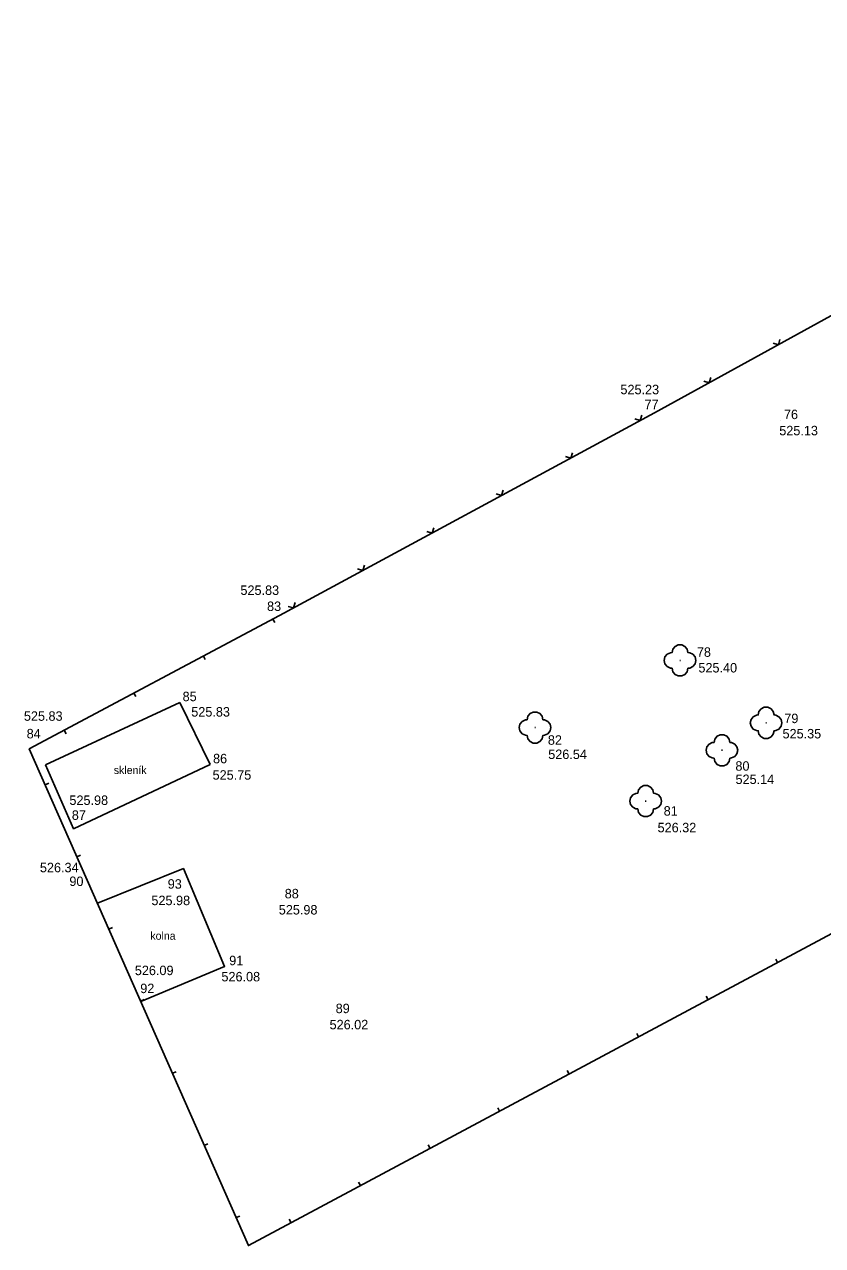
# Model space of a CAD drawing. Extents: x -871052.2 to -870965.1, y -1009970.3 to -1009910.5.
# Drawn here: x -871049.35 to -871024.03, y -1009970.27 to -1009931.56 of the extents above; entities that cross this region are included whole.
import ezdxf

# ---------------------------------------------------------------- set-up
doc = ezdxf.new("R2010")
doc.units = 0
for name, color, linetype in [('Vrstva 10', 7, 'Continuous'), ('Vrstva 13', 7, 'Continuous'), ('Vrstva 17', 7, 'Continuous'), ('Vrstva 58', 7, 'Continuous'), ('Vrstva 59', 7, 'Continuous'), ('Vrstva 60', 7, 'Continuous'), ('Vrstva 63', 7, 'Continuous')]:
    doc.layers.add(name, color=color, linetype=linetype)

msp = doc.modelspace()

# ---------------------------------------------------------------- linework, layer by layer
at = {"layer": 'Vrstva 10'}
for points in [[(-871028.05, -1009951.72), (-871028.075, -1009951.828), (-871028.145, -1009951.915), (-871028.245, -1009951.962), (-871028.3, -1009951.97), (-871028.325, -1009952.078), (-871028.395, -1009952.165), (-871028.495, -1009952.212), (-871028.608, -1009952.212), (-871028.708, -1009952.165), (-871028.778, -1009952.078), (-871028.802, -1009951.97), (-871028.858, -1009951.962), (-871028.958, -1009951.915), (-871029.028, -1009951.828), (-871029.052, -1009951.72), (-871029.028, -1009951.612), (-871028.958, -1009951.525), (-871028.858, -1009951.477), (-871028.802, -1009951.47), (-871028.778, -1009951.362), (-871028.708, -1009951.275), (-871028.608, -1009951.227), (-871028.495, -1009951.227), (-871028.395, -1009951.275), (-871028.325, -1009951.362), (-871028.3, -1009951.47), (-871028.245, -1009951.477), (-871028.145, -1009951.525), (-871028.075, -1009951.612), (-871028.05, -1009951.72)], [(-871028.562, -1009951.72), (-871028.55, -1009951.72), (-871028.538, -1009951.72)], [(-871032.65, -1009953.85), (-871032.675, -1009953.958), (-871032.745, -1009954.045), (-871032.845, -1009954.092), (-871032.9, -1009954.1), (-871032.925, -1009954.208), (-871032.995, -1009954.295), (-871033.095, -1009954.342), (-871033.208, -1009954.342), (-871033.308, -1009954.295), (-871033.378, -1009954.208), (-871033.402, -1009954.1), (-871033.458, -1009954.092), (-871033.558, -1009954.045), (-871033.628, -1009953.958), (-871033.652, -1009953.85), (-871033.628, -1009953.742), (-871033.558, -1009953.655), (-871033.458, -1009953.607), (-871033.402, -1009953.6), (-871033.378, -1009953.492), (-871033.308, -1009953.405), (-871033.208, -1009953.357), (-871033.095, -1009953.357), (-871032.995, -1009953.405), (-871032.925, -1009953.492), (-871032.9, -1009953.6), (-871032.845, -1009953.607), (-871032.745, -1009953.655), (-871032.675, -1009953.742), (-871032.65, -1009953.85)], [(-871025.32, -1009953.7), (-871025.345, -1009953.808), (-871025.415, -1009953.895), (-871025.515, -1009953.942), (-871025.57, -1009953.95), (-871025.595, -1009954.058), (-871025.665, -1009954.145), (-871025.765, -1009954.192), (-871025.878, -1009954.192), (-871025.977, -1009954.145), (-871026.048, -1009954.058), (-871026.072, -1009953.95), (-871026.128, -1009953.942), (-871026.227, -1009953.895), (-871026.298, -1009953.808), (-871026.322, -1009953.7), (-871026.298, -1009953.592), (-871026.227, -1009953.505), (-871026.128, -1009953.457), (-871026.072, -1009953.45), (-871026.048, -1009953.342), (-871025.977, -1009953.255), (-871025.878, -1009953.207), (-871025.765, -1009953.207), (-871025.665, -1009953.255), (-871025.595, -1009953.342), (-871025.57, -1009953.45), (-871025.515, -1009953.457), (-871025.415, -1009953.505), (-871025.345, -1009953.592), (-871025.32, -1009953.7)], [(-871033.162, -1009953.85), (-871033.15, -1009953.85), (-871033.138, -1009953.85)], [(-871025.832, -1009953.7), (-871025.82, -1009953.7), (-871025.808, -1009953.7)], [(-871026.72, -1009954.57), (-871026.745, -1009954.678), (-871026.815, -1009954.765), (-871026.915, -1009954.812), (-871026.97, -1009954.82), (-871026.995, -1009954.928), (-871027.065, -1009955.015), (-871027.165, -1009955.062), (-871027.278, -1009955.062), (-871027.378, -1009955.015), (-871027.448, -1009954.928), (-871027.472, -1009954.82), (-871027.528, -1009954.812), (-871027.628, -1009954.765), (-871027.698, -1009954.678), (-871027.722, -1009954.57), (-871027.698, -1009954.462), (-871027.628, -1009954.375), (-871027.528, -1009954.327), (-871027.472, -1009954.32), (-871027.448, -1009954.212), (-871027.378, -1009954.125), (-871027.278, -1009954.077), (-871027.165, -1009954.077), (-871027.065, -1009954.125), (-871026.995, -1009954.212), (-871026.97, -1009954.32), (-871026.915, -1009954.327), (-871026.815, -1009954.375), (-871026.745, -1009954.462), (-871026.72, -1009954.57)], [(-871027.232, -1009954.57), (-871027.22, -1009954.57), (-871027.208, -1009954.57)], [(-871029.14, -1009956.18), (-871029.165, -1009956.288), (-871029.235, -1009956.375), (-871029.335, -1009956.423), (-871029.39, -1009956.43), (-871029.415, -1009956.538), (-871029.485, -1009956.625), (-871029.585, -1009956.673), (-871029.698, -1009956.673), (-871029.798, -1009956.625), (-871029.868, -1009956.538), (-871029.892, -1009956.43), (-871029.948, -1009956.423), (-871030.048, -1009956.375), (-871030.118, -1009956.288), (-871030.142, -1009956.18), (-871030.118, -1009956.072), (-871030.048, -1009955.985), (-871029.948, -1009955.938), (-871029.892, -1009955.93), (-871029.868, -1009955.822), (-871029.798, -1009955.735), (-871029.698, -1009955.688), (-871029.585, -1009955.688), (-871029.485, -1009955.735), (-871029.415, -1009955.822), (-871029.39, -1009955.93), (-871029.335, -1009955.938), (-871029.235, -1009955.985), (-871029.165, -1009956.072), (-871029.14, -1009956.18)], [(-871029.652, -1009956.18), (-871029.64, -1009956.18), (-871029.628, -1009956.18)]]:
    msp.add_lwpolyline(points, dxfattribs=at)
at = {"layer": 'Vrstva 13'}
for p, q in [((-871041.463, -1009950.408), (-871041.404, -1009950.518)), ((-871043.669, -1009951.584), (-871043.611, -1009951.694)), ((-871045.876, -1009952.759), (-871045.817, -1009952.869)), ((-871048.082, -1009953.934), (-871048.024, -1009954.045)), ((-871048.691, -1009955.662), (-871048.577, -1009955.611)), ((-871047.681, -1009957.949), (-871047.567, -1009957.898)), ((-871046.672, -1009960.236), (-871046.557, -1009960.185)), ((-871025.457, -1009961.298), (-871025.516, -1009961.187)), ((-871045.662, -1009962.522), (-871045.547, -1009962.472)), ((-871027.662, -1009962.476), (-871027.721, -1009962.366)), ((-871029.867, -1009963.655), (-871029.926, -1009963.545)), ((-871044.652, -1009964.809), (-871044.537, -1009964.759)), ((-871032.071, -1009964.834), (-871032.13, -1009964.723)), ((-871034.276, -1009966.012), (-871034.335, -1009965.902)), ((-871043.642, -1009967.096), (-871043.527, -1009967.046)), ((-871036.481, -1009967.191), (-871036.54, -1009967.081)), ((-871038.686, -1009968.37), (-871038.745, -1009968.26)), ((-871042.632, -1009969.383), (-871042.517, -1009969.333)), ((-871040.89, -1009969.548), (-871040.949, -1009969.438))]:
    msp.add_line(p, q, dxfattribs=at)
for points in [[(-871005.36, -1009931.56), (-871005.91, -1009931.89), (-871021.65, -1009939.64), (-871029.36, -1009943.87), (-871041.26, -1009950.3)], [(-871002.62, -1009940.57), (-871000.21, -1009947.8), (-871042.24, -1009970.27), (-871049.193, -1009954.526), (-871041.26, -1009950.3)], [(-871025.383, -1009941.545), (-871025.432, -1009941.715), (-871025.602, -1009941.666)], [(-871027.575, -1009942.748), (-871027.624, -1009942.918), (-871027.794, -1009942.868)], [(-871029.767, -1009943.948), (-871029.817, -1009944.117), (-871029.987, -1009944.067)], [(-871031.966, -1009945.136), (-871032.017, -1009945.306), (-871032.186, -1009945.255)], [(-871034.166, -1009946.325), (-871034.216, -1009946.494), (-871034.386, -1009946.444)], [(-871036.365, -1009947.513), (-871036.416, -1009947.682), (-871036.585, -1009947.632)], [(-871038.565, -1009948.702), (-871038.615, -1009948.871), (-871038.785, -1009948.82)], [(-871040.764, -1009949.89), (-871040.815, -1009950.059), (-871040.984, -1009950.009)]]:
    msp.add_lwpolyline(points, dxfattribs=at)
at = {"layer": 'Vrstva 17'}
for p, q in [((-871044.422, -1009953.05), (-871048.684, -1009955.032)), ((-871043.456, -1009955.02), (-871044.422, -1009953.05))]:
    msp.add_line(p, q, dxfattribs=at)
for points in [[(-871043.456, -1009955.02), (-871047.79, -1009957.059), (-871048.684, -1009955.032)], [(-871047.034, -1009959.415), (-871044.306, -1009958.322), (-871042.996, -1009961.422), (-871045.655, -1009962.537)]]:
    msp.add_lwpolyline(points, dxfattribs=at)
at = {"layer": 'Vrstva 60'}
for p, q in [((-871029.36, -1009943.87), (-871029.36, -1009943.87)), ((-871025.35, -1009944.11), (-871025.35, -1009944.11)), ((-871041.26, -1009950.3), (-871041.26, -1009950.3)), ((-871041.26, -1009950.3), (-871041.26, -1009950.3)), ((-871028.55, -1009951.72), (-871028.55, -1009951.72)), ((-871044.42, -1009953.05), (-871044.42, -1009953.05)), ((-871033.15, -1009953.85), (-871033.15, -1009953.85)), ((-871025.82, -1009953.7), (-871025.82, -1009953.7)), ((-871027.22, -1009954.57), (-871027.22, -1009954.57)), ((-871043.46, -1009955.02), (-871043.46, -1009955.02)), ((-871029.64, -1009956.18), (-871029.64, -1009956.18)), ((-871047.79, -1009957.06), (-871047.79, -1009957.06)), ((-871044.31, -1009958.32), (-871044.31, -1009958.32)), ((-871047.53, -1009958.86), (-871047.53, -1009958.86)), ((-871041.18, -1009959.3), (-871041.18, -1009959.3)), ((-871043, -1009961.42), (-871043, -1009961.42)), ((-871045.65, -1009962.54), (-871045.65, -1009962.54)), ((-871039.57, -1009962.94), (-871039.57, -1009962.94))]:
    msp.add_line(p, q, dxfattribs=at)

# ---------------------------------------------------------------- texts
at = {"layer": 'Vrstva 58'}
for s, p in [('77', (-871029.678, -1009943.757)), ('76', (-871025.255, -1009944.072)), ('83', (-871041.651, -1009950.154)), ('78', (-871028.017, -1009951.607)), ('85', (-871044.33, -1009953.013)), ('79', (-871025.243, -1009953.708)), ('84', (-871049.276, -1009954.192)), ('82', (-871032.743, -1009954.394)), ('86', (-871043.364, -1009954.982)), ('80', (-871026.794, -1009955.217)), ('87', (-871047.844, -1009956.775)), ('81', (-871029.07, -1009956.641)), ('90', (-871047.921, -1009958.872)), ('93', (-871044.802, -1009958.957)), ('88', (-871041.09, -1009959.263)), ('91', (-871042.852, -1009961.383)), ('92', (-871045.673, -1009962.267)), ('89', (-871039.474, -1009962.902))]:
    msp.add_text(s, height=0.3, dxfattribs=at).set_placement(p)
at = {"layer": 'Vrstva 59'}
for s, p in [('525.23', (-871030.441, -1009943.283)), ('525.13', (-871025.403, -1009944.585)), ('525.83', (-871042.495, -1009949.645)), ('525.40', (-871027.968, -1009952.103)), ('525.83', (-871049.364, -1009953.634)), ('525.83', (-871044.055, -1009953.501)), ('525.35', (-871025.3, -1009954.193)), ('526.54', (-871032.732, -1009954.847)), ('525.75', (-871043.379, -1009955.502)), ('525.14', (-871026.791, -1009955.639)), ('525.98', (-871047.92, -1009956.302)), ('526.32', (-871029.263, -1009957.169)), ('526.34', (-871048.856, -1009958.436)), ('525.98', (-871045.319, -1009959.479)), ('525.98', (-871041.279, -1009959.775)), ('526.09', (-871045.845, -1009961.697)), ('526.08', (-871043.098, -1009961.895)), ('526.02', (-871039.668, -1009963.415))]:
    msp.add_text(s, height=0.3, dxfattribs=at).set_placement(p)
at = {"layer": 'Vrstva 63'}
for s, p in [('skleník', (-871046.512, -1009955.323)), ('kolna', (-871045.352, -1009960.575))]:
    msp.add_text(s, height=0.25, dxfattribs=at).set_placement(p)

doc.saveas('drawing.dxf')
